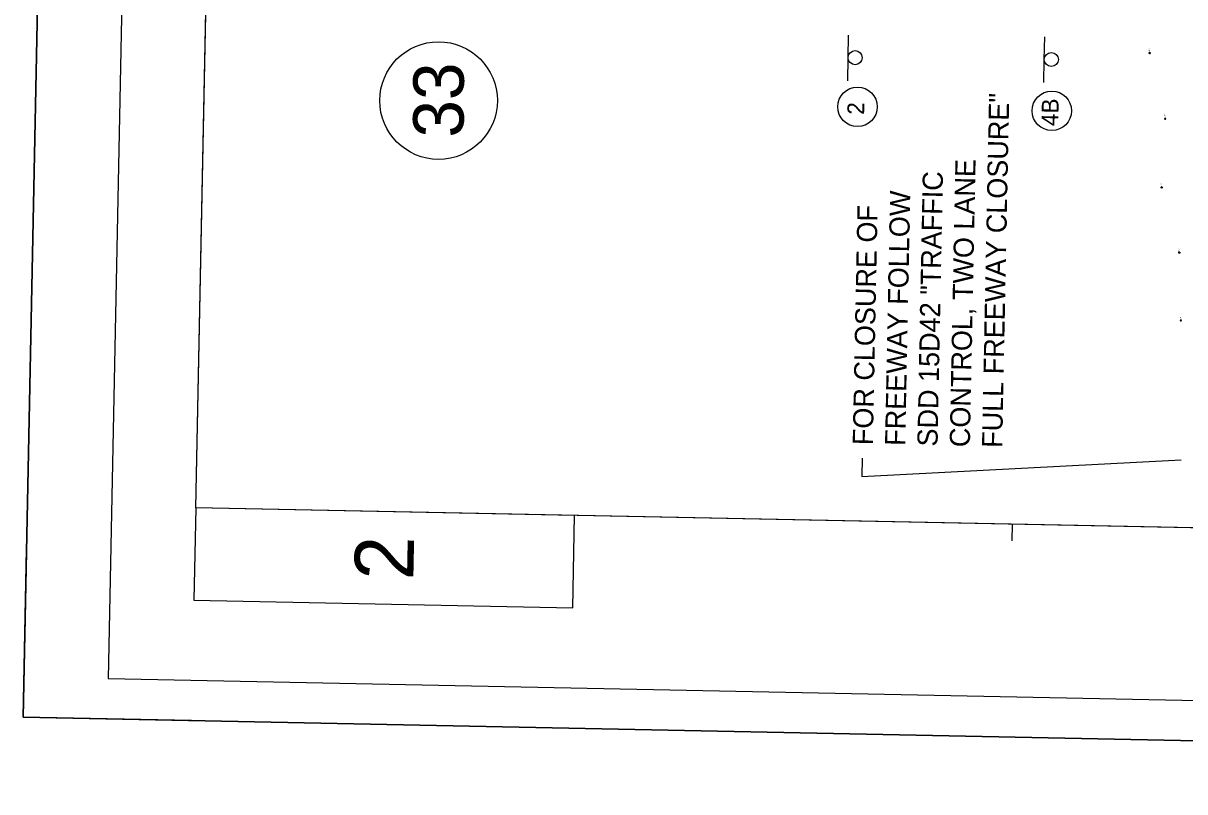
# Model space of a CAD drawing. Extents: x 345549 to 379569, y 127949 to 230467.
# Drawn here: x 345549 to 355897, y 178813 to 185661 of the extents above; entities that cross this region are included whole.
import ezdxf

# ---------------------------------------------------------------- set-up
doc = ezdxf.new("R2010")
doc.units = 0
for name, color, linetype in [('CA-TEXT', 7, 'Continuous'), ('E_SOIL_BORE1 [KAPUR_CADDS_LEVELS]', 7, 'Continuous'), ('E_SOIL_BORE2 [KAPUR_CADDS_LEVELS]', 7, 'Continuous'), ('P_MARK', 7, 'Continuous'), ('P_MISC_NoPlot', 7, 'Continuous'), ('P_MISC_TXT', 7, 'Continuous'), ('P_RDWY_Text', 7, 'Continuous'), ('PLT_Sheet_Border', 7, 'Continuous'), ('PLT_Sheet_Info', 7, 'Continuous'), ('SIGNS-POLES', 7, 'Continuous')]:
    doc.layers.add(name, color=color, linetype=linetype)

msp = doc.modelspace()

# ---------------------------------------------------------------- linework, layer by layer
at = {"layer": 'CA-TEXT'}
msp.add_line((349249, 184972), (349249, 184972), dxfattribs=at)
for centre, radius in [((349249, 184972), 524), ((352981, 184916), 176), ((354712, 184881), 176)]:
    msp.add_circle(centre, radius, dxfattribs=at)
at = {"layer": 'P_MARK'}
for p, q in [((355579, 185396), (355589, 185396)), ((355584, 185401), (355584, 185391)), ((355723, 184814), (355723, 184804)), ((355718, 184809), (355728, 184809)), ((355686, 184197), (355696, 184197)), ((355691, 184202), (355691, 184192)), ((355843, 183617), (355853, 183617)), ((355848, 183622), (355848, 183612)), ((355857, 183012), (355867, 183012)), ((355862, 183017), (355862, 183007))]:
    msp.add_line(p, q, dxfattribs=at)
for centre in [(355584, 185396), (355723, 184809), (355691, 184197), (355848, 183617), (355862, 183012)]:
    msp.add_circle(centre, 5, dxfattribs=at)
for centre, radius, start, end in [((355584, 185396), 4.5, 89.9869, 179.9869), ((355584, 185396), 4, 89.9869, 179.9869), ((355584, 185396), 3.5, 89.9869, 179.9869), ((355584, 185396), 3, 89.9869, 179.9869), ((355584, 185396), 2.5, 89.9869, 179.9869), ((355584, 185396), 2, 89.9869, 179.9869), ((355584, 185396), 1.5, 89.9869, 179.9869), ((355584, 185396), 1, 89.9869, 179.9869), ((355584, 185396), 0.5, 89.9869, 179.9869), ((355584, 185396), 4.5, 269.9869, 359.9869), ((355584, 185396), 4, 269.9869, 359.9869), ((355584, 185396), 3.5, 269.9869, 359.9869), ((355584, 185396), 3, 269.9869, 359.9869), ((355584, 185396), 2.5, 269.9869, 359.9869), ((355584, 185396), 2, 269.9869, 359.9869), ((355584, 185396), 1.5, 269.9869, 359.9869), ((355584, 185396), 1, 269.9869, 359.9869), ((355584, 185396), 0.5, 269.9869, 359.9869), ((355723, 184809), 4.5, 89.9869, 179.9869), ((355723, 184809), 4, 89.9869, 179.9869), ((355723, 184809), 3.5, 89.9869, 179.9869), ((355723, 184809), 3, 89.9869, 179.9869), ((355723, 184809), 2.5, 89.9869, 179.9869), ((355723, 184809), 2, 89.9869, 179.9869), ((355723, 184809), 1.5, 89.9869, 179.9869), ((355723, 184809), 1, 89.9869, 179.9869), ((355723, 184809), 0.5, 89.9869, 179.9869), ((355723, 184809), 4.5, 269.9869, 359.9869), ((355723, 184809), 4, 269.9869, 359.9869), ((355723, 184809), 3.5, 269.9869, 359.9869), ((355723, 184809), 3, 269.9869, 359.9869), ((355723, 184809), 2.5, 269.9869, 359.9869), ((355723, 184809), 2, 269.9869, 359.9869), ((355723, 184809), 1.5, 269.9869, 359.9869), ((355723, 184809), 1, 269.9869, 359.9869), ((355723, 184809), 0.5, 269.9869, 359.9869), ((355691, 184197), 4.5, 89.9869, 179.9869), ((355691, 184197), 4, 89.9869, 179.9869), ((355691, 184197), 3.5, 89.9869, 179.9869), ((355691, 184197), 3, 89.9869, 179.9869), ((355691, 184197), 2.5, 89.9869, 179.9869), ((355691, 184197), 2, 89.9869, 179.9869), ((355691, 184197), 1.5, 89.9869, 179.9869), ((355691, 184197), 1, 89.9869, 179.9869), ((355691, 184197), 0.5, 89.9869, 179.9869), ((355691, 184197), 4.5, 269.9869, 359.9869), ((355691, 184197), 4, 269.9869, 359.9869), ((355691, 184197), 3.5, 269.9869, 359.9869), ((355691, 184197), 3, 269.9869, 359.9869), ((355691, 184197), 2.5, 269.9869, 359.9869), ((355691, 184197), 2, 269.9869, 359.9869), ((355691, 184197), 1.5, 269.9869, 359.9869), ((355691, 184197), 1, 269.9869, 359.9869), ((355691, 184197), 0.5, 269.9869, 359.9869), ((355848, 183617), 4.5, 89.9869, 179.9869), ((355848, 183617), 4, 89.9869, 179.9869), ((355848, 183617), 3.5, 89.9869, 179.9869), ((355848, 183617), 3, 89.9869, 179.9869), ((355848, 183617), 2.5, 89.9869, 179.9869), ((355848, 183617), 2, 89.9869, 179.9869), ((355848, 183617), 1.5, 89.9869, 179.9869), ((355848, 183617), 1, 89.9869, 179.9869), ((355848, 183617), 4.5, 269.9869, 359.9869), ((355848, 183617), 4, 269.9869, 359.9869), ((355848, 183617), 3.5, 269.9869, 359.9869), ((355848, 183617), 3, 269.9869, 359.9869), ((355848, 183617), 2.5, 269.9869, 359.9869), ((355848, 183617), 2, 269.9869, 359.9869), ((355848, 183617), 1.5, 269.9869, 359.9869), ((355848, 183617), 1, 269.9869, 359.9869), ((355848, 183617), 0.5, 269.9869, 359.9869), ((355848, 183617), 0.5, 89.9869, 179.9869), ((355862, 183012), 4.5, 89.9869, 179.9869), ((355862, 183012), 4, 89.9869, 179.9869), ((355862, 183012), 3.5, 89.9869, 179.9869), ((355862, 183012), 3, 89.9869, 179.9869), ((355862, 183012), 2.5, 89.9869, 179.9869), ((355862, 183012), 2, 89.9869, 179.9869), ((355862, 183012), 1.5, 89.9869, 179.9869), ((355862, 183012), 1, 89.9869, 179.9869), ((355862, 183012), 0.5, 89.9869, 179.9869), ((355862, 183012), 4.5, 269.9869, 359.9869), ((355862, 183012), 4, 269.9869, 359.9869), ((355862, 183012), 3.5, 269.9869, 359.9869), ((355862, 183012), 3, 269.9869, 359.9869), ((355862, 183012), 2.5, 269.9869, 359.9869), ((355862, 183012), 2, 269.9869, 359.9869), ((355862, 183012), 1.5, 269.9869, 359.9869), ((355862, 183012), 1, 269.9869, 359.9869), ((355862, 183012), 0.5, 269.9869, 359.9869)]:
    msp.add_arc(centre, radius, start, end, dxfattribs=at)
at = {"layer": 'P_MISC_NoPlot'}
msp.add_lwpolyline([(347087, 181344), (347770, 215283), (369369, 214831), (369345, 213590), (376990, 213459), (376331, 180755)], close=True, dxfattribs=at)
at = {"layer": 'P_MISC_TXT'}
for p, q in [((353024, 181787), (353021, 181621)), ((353021, 181621), (355864, 181770))]:
    msp.add_line(p, q, dxfattribs=at)
at = {"layer": 'P_RDWY_Text'}
msp.add_lwpolyline([(345549, 179477), (346576, 230467), (379569, 229803), (378542, 178813)], close=True, dxfattribs=at)
at = {"layer": 'PLT_Sheet_Border'}
for points in [[(378542, 178813), (379569, 229803), (346576, 230467), (345549, 179477)], [(377800, 179188), (378799, 228828), (347306, 229462), (346306, 179822)]]:
    msp.add_lwpolyline(points, close=True, dxfattribs=at)
at = {"layer": 'PLT_Sheet_Info'}
for p, q in [((347087, 181344), (348038, 228585)), ((377081, 180740), (347087, 181344)), ((354360, 181198), (354357, 181048)), ((345549, 179477), (345579, 180977)), ((347049, 179447), (345549, 179477))]:
    msp.add_line(p, q, dxfattribs=at)
msp.add_lwpolyline([(347087, 181344), (347070, 180520), (350445, 180452), (350461, 181276)], close=True, dxfattribs=at)
at = {"layer": 'SIGNS-POLES'}
for p, q in [((352898, 185353), (352902, 185556)), ((354645, 185337), (354649, 185540)), ((352894, 185149), (352897, 185352)), ((354641, 185133), (354644, 185336))]:
    msp.add_line(p, q, dxfattribs=at)
for centre in [(352960, 185354), (354708, 185338)]:
    msp.add_circle(centre, 62.6, dxfattribs=at)

# ---------------------------------------------------------------- texts
at = {"layer": 'CA-TEXT'}
for s, height, rotation, p in [('33', 450, 89.767, (349472, 184641)), ('2', 150, 88.8468, (353040, 184844)), ('4B', 150, 88.8468, (354769, 184744))]:
    msp.add_text(s, height=height, rotation=rotation, dxfattribs=at).set_placement(p)
at = {"layer": 'E_SOIL_BORE1 [KAPUR_CADDS_LEVELS]'}
for s, p in [('B104', (355727, 184817)), ('B101', (355694, 184204)), ('B102', (355851, 183624))]:
    msp.add_text(s, height=10, rotation=98.957, dxfattribs=at).set_placement(p)
at = {"layer": 'E_SOIL_BORE2 [KAPUR_CADDS_LEVELS]'}
for s, p in [('B103', (355588, 185404)), ('B99', (355866, 183022))]:
    msp.add_text(s, height=10, rotation=98.957, dxfattribs=at).set_placement(p)
at = {"layer": 'P_MISC_TXT'}
for s, p in [('FULL FREEWAY CLOSURE"', (354270, 181876)), ('CONTROL, TWO LANE', (353982, 181882)), ('SDD 15D42 "TRAFFIC', (353694, 181888)), ('FREEWAY FOLLOW', (353406, 181894)), ('FOR CLOSURE OF', (353118, 181900))]:
    msp.add_text(s, height=180, rotation=88.8468, dxfattribs=at).set_placement(p)
at = {"layer": 'PLT_Sheet_Info'}
msp.add_text('2', height=525, rotation=88.8462, dxfattribs=at).set_placement((349024, 180696))

doc.saveas('drawing.dxf')
